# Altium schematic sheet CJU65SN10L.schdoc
size 127 x 101 mm
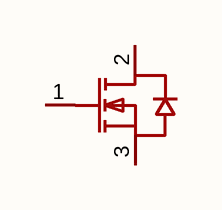
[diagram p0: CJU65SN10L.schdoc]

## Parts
Q?  cju65sn10l  [TO-252-2_L6.6-W6.1-P4.57-LS10.0-BR-1]  (value not drawn)

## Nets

Not connected (* = marked no-connect by the designer): Q? 1(G) 2(D) 3(S)

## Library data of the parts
Q? = cju65sn10l: 数量:1个N沟道;漏源电压(Vdss):100V;连续漏极电流(Id):65A;导通电阻(RDS(on)):11mΩ@10V;耗散功率(Pd):125W;阈值电压(Vgs(th)):2.5V;; Manufacturer: CJ(江苏长电/长晶); AddInBom: yes; ModelId: 4113ec4a058842b08e2585e7304bd9b4; ModelTransform: 401.574,259.842,0,0,0,0,-36.417,0,0; Number: 1个N沟道; Drain to Source Voltage: 100V; Current - Continuous Drain(Id): 65A; Pd - Power Dissipation: 125W; Gate Threshold Voltage (Vgs(th)): 2.5V; Gate Charge(Qg): 23.4nC@10V; Input Capacitance(Ciss): 1.285nF; Reverse Transfer Capacitance (Crss@Vds): 5.5pF; Type: N沟道; Output Capacitance(Coss): 275pF; Vgs: ±20V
